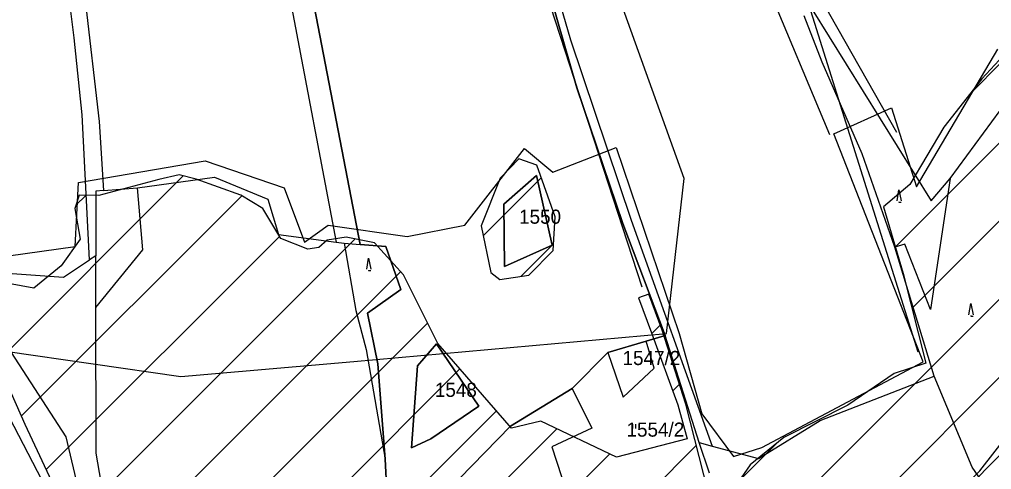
# Model space of a CAD drawing. Extents: x -564810 to -550519, y -1045831 to -1034011.
# Drawn here: x -553314.2 to -552963, y -1039367.3 to -1039204.5 of the extents above; entities that cross this region are included whole.
import ezdxf

# ---------------------------------------------------------------- set-up
doc = ezdxf.new("R2010")
doc.units = 0
for name, color, linetype in [('Biokoridory', 7, 'Continuous'), ('Interakční prvky', 7, 'Continuous'), ('KN stav', 7, 'Continuous'), ('Lesní porost', 7, 'Continuous'), ('Parcelní čísla', 7, 'Continuous'), ('STG', 7, 'Continuous'), ('Vedení VN', 7, 'Continuous'), ('Vrstva 4', 7, 'Continuous'), ('Vrstva 5', 7, 'Continuous'), ('zamokř ploch', 7, 'Continuous')]:
    doc.layers.add(name, color=color, linetype=linetype)

msp = doc.modelspace()

# ---------------------------------------------------------------- linework, layer by layer
at = {"layer": 'Biokoridory'}
for points in [[(-553021.4, -1039246.26), (-553044.43, -1039191.19), (-553059, -1039150.44), (-553067.62, -1039084.91), (-553075.19, -1039036.75), (-553090.23, -1038976.5), (-553111.52, -1038912.08)], [(-553092.12, -1038916.08), (-553079.25, -1038949.34), (-553065.42, -1039012.48), (-553053.18, -1039060.27), (-553043.26, -1039137.75), (-553024.06, -1039198.14), (-552997.35, -1039245.25)]]:
    msp.add_lwpolyline(points, dxfattribs=at)
at = {"layer": 'Interakční prvky'}
for points in [[(-553089.19, -1039301.26), (-553123.95, -1039194.26), (-553160.79, -1039004.43), (-553173.27, -1038926.68), (-553194.07, -1038907.06), (-553252.3, -1038904.68)], [(-553091.47, -1038937.22), (-553059.09, -1039066.93), (-553048.99, -1039135.59), (-552989.65, -1039324.75)]]:
    msp.add_lwpolyline(points, dxfattribs=at)
at = {"layer": 'KN stav'}
for p, q in [((-553299.79, -1039115.04), (-553285.45, -1039241.42)), ((-553294.47, -1039211.22), (-553300.27, -1039162.1)), ((-553123.3, -1039183.69), (-553115.12, -1039211.94)), ((-553210.06, -1039187.29), (-553191.05, -1039285.86)), ((-553191.05, -1039285.86), (-553210.06, -1039187.29)), ((-553125.14, -1039186.08), (-553112.82, -1039229.31)), ((-553112.82, -1039229.31), (-553125.14, -1039186.08)), ((-553216.24, -1039198.06), (-553199.77, -1039285.03)), ((-553027.74, -1039200.91), (-552984.8, -1039270.08)), ((-553024.19, -1039220.02), (-553030.62, -1039203.26)), ((-553291.52, -1039238.96), (-553294.47, -1039211.22)), ((-553115.12, -1039211.94), (-553093.15, -1039277.04)), ((-553009.71, -1039253.07), (-553024.19, -1039220.02)), ((-553112.82, -1039229.31), (-553096.14, -1039278.25)), ((-553096.14, -1039278.25), (-553112.82, -1039229.31)), ((-552977.88, -1039262.01), (-552956.82, -1039233.32)), ((-553288.88, -1039291.44), (-553291.52, -1039238.96)), ((-553285.45, -1039241.42), (-553283.83, -1039266.43)), ((-552997.96, -1039286.81), (-553009.71, -1039253.07)), ((-553127.42, -1039260.96), (-553139.16, -1039271.3)), ((-553139.16, -1039271.3), (-553127.42, -1039260.96)), ((-553121.67, -1039286.1), (-553127.42, -1039260.96)), ((-553127.42, -1039260.96), (-553121.67, -1039286.1)), ((-553271.51, -1039265.42), (-553243.74, -1039261.6)), ((-553243.74, -1039261.6), (-553224.5, -1039269.47)), ((-552984.8, -1039270.08), (-552977.88, -1039262.01)), ((-553283.83, -1039266.43), (-553286.63, -1039266.66)), ((-553286.63, -1039266.66), (-553286.62, -1039289.93)), ((-553283.83, -1039266.43), (-553271.51, -1039265.42)), ((-553224.5, -1039269.47), (-553220.62, -1039282.3)), ((-553139.16, -1039271.3), (-553138.93, -1039293.79)), ((-553138.93, -1039293.79), (-553139.16, -1039271.3)), ((-553096.14, -1039278.25), (-553080.92, -1039318.81)), ((-553080.92, -1039318.81), (-553096.14, -1039278.25)), ((-553093.15, -1039277.04), (-553063.89, -1039358.77)), ((-553220.62, -1039282.3), (-553199.77, -1039285.03)), ((-553199.77, -1039285.03), (-553196.83, -1039285.42)), ((-553196.83, -1039285.42), (-553191.05, -1039285.86)), ((-553191.05, -1039285.86), (-553181.88, -1039286.57)), ((-553181.88, -1039286.57), (-553191.05, -1039285.86)), ((-553181.88, -1039286.57), (-553176.45, -1039302.11)), ((-553176.45, -1039302.11), (-553181.88, -1039286.57)), ((-553138.93, -1039293.79), (-553121.67, -1039286.1)), ((-553121.67, -1039286.1), (-553138.93, -1039293.79)), ((-552983.73, -1039333.51), (-552997.96, -1039286.81)), ((-553298.29, -1039297.74), (-553288.88, -1039291.44)), ((-553286.62, -1039289.93), (-553288.88, -1039291.44)), ((-553316.84, -1039296.42), (-553298.29, -1039297.74)), ((-553176.45, -1039302.11), (-553188.5, -1039310.66)), ((-553188.5, -1039310.66), (-553176.45, -1039302.11)), ((-553188.5, -1039310.66), (-553184.71, -1039329.06)), ((-553184.71, -1039329.06), (-553188.5, -1039310.66)), ((-553320.15, -1039320.53), (-553297.48, -1039355.44)), ((-553087.77, -1039320.83), (-553101.62, -1039324.96)), ((-553101.62, -1039324.96), (-553087.77, -1039320.83)), ((-553080.92, -1039318.81), (-553087.77, -1039320.83)), ((-553087.77, -1039320.83), (-553080.92, -1039318.81)), ((-553084.88, -1039330.54), (-553087.77, -1039320.83)), ((-553068.6, -1039357.52), (-553080.92, -1039318.81)), ((-553163.53, -1039321.75), (-553170.37, -1039329.81)), ((-553170.37, -1039329.81), (-553163.53, -1039321.75)), ((-553148.23, -1039344.37), (-553163.53, -1039321.75)), ((-553163.53, -1039321.75), (-553148.23, -1039344.37)), ((-553101.62, -1039324.96), (-553114.54, -1039337.98)), ((-553114.54, -1039337.98), (-553101.62, -1039324.96)), ((-553101.62, -1039324.96), (-553096.02, -1039341.08)), ((-553184.71, -1039329.06), (-553182.11, -1039363.44)), ((-553182.11, -1039363.44), (-553184.71, -1039329.06)), ((-553170.37, -1039329.81), (-553172.59, -1039359.41)), ((-553172.59, -1039359.41), (-553170.37, -1039329.81)), ((-553096.02, -1039341.08), (-553084.88, -1039330.54)), ((-553024.9, -1039349.46), (-552983.73, -1039333.51)), ((-553136.76, -1039351.58), (-553114.54, -1039337.98)), ((-553114.54, -1039337.98), (-553136.76, -1039351.58)), ((-553114.54, -1039337.98), (-553107.43, -1039352.25)), ((-553165.54, -1039356.12), (-553148.23, -1039344.37)), ((-553148.23, -1039344.37), (-553165.54, -1039356.12)), ((-553167.91, -1039383.44), (-553136.76, -1039351.58)), ((-553136.76, -1039351.58), (-553167.91, -1039383.44)), ((-553107.43, -1039352.25), (-553121.87, -1039358.98)), ((-553047.22, -1039363.21), (-553024.9, -1039349.46)), ((-553297.48, -1039355.44), (-553291.23, -1039381.95)), ((-553172.59, -1039359.41), (-553165.54, -1039356.12)), ((-553165.54, -1039356.12), (-553172.59, -1039359.41)), ((-553121.87, -1039358.98), (-553115.2, -1039379.19)), ((-553064.81, -1039368.52), (-553068.6, -1039357.52)), ((-553068.6, -1039357.52), (-553063.89, -1039358.77)), ((-553063.89, -1039358.77), (-553047.22, -1039363.21)), ((-553182.11, -1039363.44), (-553180.83, -1039385.61)), ((-553180.83, -1039385.61), (-553182.11, -1039363.44))]:
    msp.add_line(p, q, dxfattribs=at)
at = {"layer": 'Lesní porost'}
for p, q in [((-552960.22, -1039219.29), (-552966.44, -1039226.02)), ((-552966.44, -1039226.02), (-552980.24, -1039243.47)), ((-552980.24, -1039243.47), (-552992.44, -1039264.26)), ((-553133.71, -1039254.93), (-553140.48, -1039261.86)), ((-553127.31, -1039257.27), (-553133.71, -1039254.93)), ((-553120.69, -1039275.91), (-553127.31, -1039257.27)), ((-553256.55, -1039260.74), (-553263.87, -1039262.36)), ((-553250.31, -1039262.26), (-553256.55, -1039260.74)), ((-553263.87, -1039262.36), (-553285.48, -1039268.19)), ((-553234.21, -1039268.08), (-553250.31, -1039262.26)), ((-553140.48, -1039261.86), (-553147.41, -1039279.12)), ((-553146.64, -1039282.78), (-553125.69, -1039261.83)), ((-552992.44, -1039264.26), (-553001.95, -1039272.31)), ((-552992.44, -1039264.26), (-553001.95, -1039272.31)), ((-553292.68, -1039268.08), (-553294.19, -1039272.93)), ((-553285.48, -1039268.19), (-553292.68, -1039268.08)), ((-553226.32, -1039272.92), (-553234.21, -1039268.08)), ((-553294.19, -1039272.93), (-553292.23, -1039283.97)), ((-553219.8, -1039283.77), (-553226.32, -1039272.92)), ((-553001.95, -1039272.31), (-552994.88, -1039296.35)), ((-553121.36, -1039288.01), (-553120.69, -1039275.91)), ((-553147.41, -1039279.12), (-553143.85, -1039296.03)), ((-553292.23, -1039283.97), (-553299.1, -1039293.55)), ((-553209.96, -1039287.61), (-553219.8, -1039283.77)), ((-553202.99, -1039284.38), (-553206.03, -1039287.03)), ((-553196.18, -1039283.23), (-553202.99, -1039284.38)), ((-553185.94, -1039285.3), (-553196.18, -1039283.23)), ((-553175.45, -1039296.81), (-553185.94, -1039285.3)), ((-553132.96, -1039297.39), (-553121.23, -1039285.66)), ((-553206.03, -1039287.03), (-553209.96, -1039287.61)), ((-553130.15, -1039296.96), (-553121.36, -1039288.01)), ((-553299.1, -1039293.55), (-553309.02, -1039301.73)), ((-553143.85, -1039296.03), (-553140.65, -1039298.57)), ((-552994.88, -1039296.35), (-552986.64, -1039328.75)), ((-553163.06, -1039321.69), (-553175.45, -1039296.81)), ((-553140.65, -1039298.57), (-553130.15, -1039296.96)), ((-553309.02, -1039301.73), (-553318.15, -1039300)), ((-553086.83, -1039303.85), (-553090.49, -1039305.21)), ((-553090.49, -1039305.21), (-553085.82, -1039317.82)), ((-553082.01, -1039316.84), (-553086.83, -1039303.85)), ((-553073.45, -1039343.63), (-553082.01, -1039316.84)), ((-553325.51, -1039320.96), (-553312.26, -1039350.9)), ((-553085.82, -1039317.82), (-553076.36, -1039343.88)), ((-553136.42, -1039352.27), (-553163.06, -1039321.69)), ((-552986.64, -1039328.75), (-552998.1, -1039332.49)), ((-552998.1, -1039332.49), (-553014.83, -1039344)), ((-553076.36, -1039343.88), (-553072.9, -1039356.11)), ((-553065.08, -1039376.47), (-553073.45, -1039343.63)), ((-553014.83, -1039344), (-553038.04, -1039355.71)), ((-553312.26, -1039350.9), (-553299.96, -1039377.02)), ((-553125.8, -1039349.73), (-553136.42, -1039352.27)), ((-553098.46, -1039362.79), (-553125.8, -1039349.73)), ((-553072.9, -1039356.11), (-553098.46, -1039362.79)), ((-553038.04, -1039355.71), (-553050.15, -1039365.54)), ((-553050.15, -1039365.54), (-553057.4, -1039376))]:
    msp.add_line(p, q, dxfattribs=at)
at = {"layer": 'STG'}
for points in [[(-553077.37, -1039475.17), (-553074.61, -1039459.55), (-553032.36, -1039426.47), (-553011.23, -1039412.69), (-552967.14, -1039367.67), (-552937.75, -1039330), (-552909.27, -1039281.3), (-552907.43, -1039273.03), (-552900.09, -1039209.63), (-552915.7, -1039154.51), (-552930.4, -1039090.19), (-552934.99, -1039017.61), (-552932.23, -1038958.8), (-552923.97, -1038914.7), (-552946.01, -1038887.14), (-552963.47, -1038886.22), (-552998.37, -1038894.49), (-553092.98, -1038892.65), (-553109.51, -1038893.57)], [(-553677.45, -1039296.92), (-553596.62, -1039301.51), (-553502.93, -1039306.11), (-553457.92, -1039305.19), (-553397.3, -1039309.78), (-553319.22, -1039324.48), (-553255.84, -1039333.67), (-553193.38, -1039328.16), (-553080.4, -1039318.05), (-553073.97, -1039262.01), (-553107.03, -1039170.13), (-553126.32, -1039103.05), (-553143.78, -1039028.63), (-553170.41, -1038977.18), (-553210.83, -1038911.03), (-553216.34, -1038906.43), (-553289.83, -1038923.89), (-553340.35, -1038942.26), (-553416.59, -1038970.75), (-553514.87, -1038998.31), (-553617.75, -1039014.85), (-553673.78, -1039026.79)]]:
    msp.add_lwpolyline(points, dxfattribs=at)
at = {"layer": 'Vedení VN'}
for p, q in [((-552970.59, -1039231.27), (-552959.07, -1039219.75)), ((-552997.72, -1039286.69), (-552947.7, -1039236.67)), ((-553322.24, -1039328.36), (-553255, -1039261.12)), ((-553313.56, -1039347.96), (-553233.88, -1039268.28)), ((-553293.78, -1039271.62), (-553290.28, -1039268.12)), ((-552991.68, -1039308.93), (-552957.12, -1039274.37)), ((-553336.17, -1039427.14), (-553192.92, -1039283.89)), ((-553304.56, -1039367.25), (-553220.28, -1039282.97)), ((-553314.2, -1039433.45), (-553176.45, -1039295.71)), ((-553120.25, -1039465.78), (-552956.47, -1039302)), ((-553300.61, -1039448.15), (-553166.75, -1039314.29)), ((-553085.71, -1039318.11), (-553082.67, -1039315.06)), ((-553280.24, -1039456.07), (-553155.05, -1039330.88)), ((-553089.3, -1039463.12), (-552958.87, -1039332.69)), ((-553078.18, -1039338.86), (-553075.75, -1039336.43)), ((-553272.62, -1039476.73), (-553141.89, -1039346)), ((-553257.54, -1039489.94), (-553120.07, -1039352.47)), ((-553194.47, -1039483.43), (-553069.64, -1039358.6)), ((-553054.35, -1039371.59), (-553040.28, -1039357.53)), ((-553234.72, -1039495.4), (-553100.93, -1039361.61)), ((-553057.19, -1039459.29), (-552958.89, -1039360.99))]:
    msp.add_line(p, q, dxfattribs=at)
at = {"layer": 'Vrstva 4'}
for p, q in [((-552977.88, -1039262.01), (-552985.07, -1039309.34)), ((-553269.67, -1039287.81), (-553271.51, -1039265.42)), ((-553196.83, -1039285.42), (-553192.72, -1039309.81)), ((-552994.34, -1039285.78), (-552997.96, -1039286.81)), ((-552985.07, -1039309.34), (-552994.34, -1039285.78)), ((-553286.6, -1039308.62), (-553269.67, -1039287.81)), ((-553286.6, -1039308.62), (-553286.62, -1039289.93)), ((-553286.55, -1039361.37), (-553286.6, -1039308.62)), ((-553192.72, -1039309.81), (-553188.98, -1039323.82)), ((-553188.98, -1039323.82), (-553182.11, -1039363.45)), ((-552969.99, -1039366.36), (-552983.73, -1039333.51)), ((-553282.82, -1039382.27), (-553286.55, -1039361.37)), ((-552963.07, -1039376.29), (-552969.99, -1039366.36))]:
    msp.add_line(p, q, dxfattribs=at)
at = {"layer": 'Vrstva 5'}
for points in [[(-553318.14, -1039289.94), (-553294.07, -1039286.67), (-553292.85, -1039263.42), (-553247.15, -1039255.66), (-553218.59, -1039265.46), (-553211.24, -1039285.04), (-553202.68, -1039278.92), (-553174.12, -1039283), (-553153.31, -1039278.92), (-553131.68, -1039251.18), (-553121.48, -1039259.74), (-553098.63, -1039250.77), (-553075.78, -1039318.09), (-553067.62, -1039347.06), (-553056.2, -1039362.56), (-553046, -1039359.3), (-552987.65, -1039328.29), (-553019.89, -1039245.87), (-552999.08, -1039236.49), (-552990.1, -1039265.05), (-552960.72, -1039215.27)], [(-553343.03, -1039381.33), (-553302.64, -1039377.66), (-553334.87, -1039315.64)]]:
    msp.add_lwpolyline(points, dxfattribs=at)
at = {"layer": 'zamokř ploch'}
for p, q in [((-553092.65, -1039350.85), (-553092.65, -1039352.35)), ((-553091.65, -1039350.85), (-553091.65, -1039352.35))]:
    msp.add_line(p, q, dxfattribs=at)
for points in [[(-552997.11, -1039270.11), (-552996.42, -1039266.11), (-552995.61, -1039270.11)], [(-552996.42, -1039270.41), (-552996.42, -1039270.61), (-552995.61, -1039270.61)], [(-553188.73, -1039294.82), (-553188.03, -1039290.82), (-553187.23, -1039294.82)], [(-553188.03, -1039295.12), (-553188.03, -1039295.32), (-553187.23, -1039295.32)], [(-552971.14, -1039311.27), (-552970.44, -1039307.27), (-552969.64, -1039311.27)], [(-552970.44, -1039311.57), (-552970.44, -1039311.77), (-552969.64, -1039311.77)]]:
    msp.add_lwpolyline(points, dxfattribs=at)

# ---------------------------------------------------------------- texts
at = {"layer": 'Parcelní čísla'}
for s, p in [('1550', (-553133.68, -1039278.39)), ('1547/2', (-553096.3, -1039329.47)), ('1548', (-553164.11, -1039340.98)), ('1554/2', (-553094.86, -1039355.36))]:
    msp.add_text(s, height=5.1, dxfattribs=at).set_placement(p)

doc.saveas('drawing.dxf')
